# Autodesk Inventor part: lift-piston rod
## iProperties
Author: vincent molino
Shininess: 86.0
Angle Display Precision: 2
Document Length Units: 11272
Document Angle Units: 11286
Document Time Units: 11279
Document Mass Units: 11290
Document Length Units Precision: 3
Document Angle Units Precision: 2
Compacted: True
PropertySet Name: _Private Model Information
Created: 2002-01
Part Number: lift-piston rod
Document SubType Name: Modeling
Designer: vincent molino
Control State: 0
Master: False
Checked Out: False
PropertySet Name: Design Tracking Control
Density: 0.0
Volumn: 0.0
Area: 0.0
PropertySet Name: Model Information
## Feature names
1. Extrusion1
